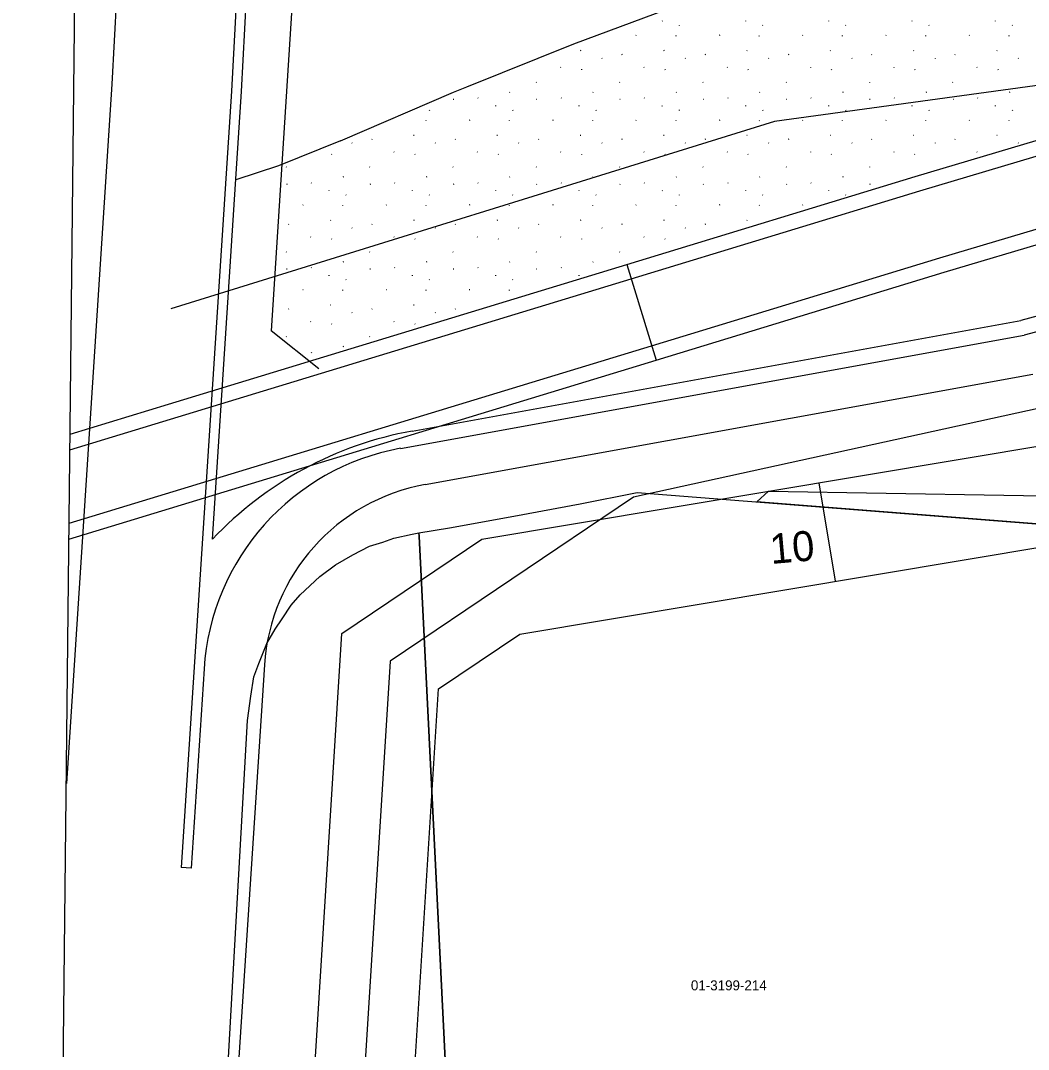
# Model space of a CAD drawing. Extents: x 419396 to 421519, y 4453567 to 4456767.
# Drawn here: x 420195.1 to 420295.9, y 4454723.5 to 4454826.5 of the extents above; entities that cross this region are included whole.
import ezdxf

# ---------------------------------------------------------------- set-up
doc = ezdxf.new("R2010")
doc.units = 0
for name, color, linetype in [('0_KADASTRO', 7, 'Continuous'), ('ADAKENARI1000', 7, 'Continuous'), ('ADAKENARI_ALT', 7, 'Continuous'), ('KALDIRIM', 7, 'Continuous'), ('KALDIRIM_ALT', 7, 'Continuous'), ('Level 20', 7, 'Continuous'), ('Level 29', 7, 'Continuous'), ('Level 41', 7, 'Continuous'), ('Level 9', 7, 'Continuous'), ('Y_Lejant', 7, 'Continuous')]:
    doc.layers.add(name, color=color, linetype=linetype)

msp = doc.modelspace()

# ---------------------------------------------------------------- linework, layer by layer
at = {"layer": '0_KADASTRO'}
for points in [[(420234.94, 4454775.21), (420237.99, 4454775.74), (420244.42, 4454776.89), (420251.07, 4454778.12), (420256.76, 4454779.25), (420319.17, 4454774.37), (420311.2, 4454734.75), (420308.37, 4454720.37), (420303.03, 4454697.63), (420301.63, 4454668.31), (420262.04, 4454668.65), (420253.02, 4454668.72), (420240.25, 4454669.24), (420238.25, 4454709.08), (420234.96, 4454774.88)], [(420268.76, 4454778.31), (420269.91, 4454779.39), (420317, 4454778.58), (420319.9, 4454775.53), (420318.59, 4454733.9), (420311.2, 4454734.75), (420319.17, 4454774.37)], [(420213.35, 4454677.72), (420217.79, 4454756.43), (420218.11, 4454758.88), (420218.44, 4454760.82), (420218.93, 4454762.13), (420219.72, 4454764.15), (420220.56, 4454765.58), (420221.26, 4454766.63), (420222.15, 4454767.98), (420223.07, 4454769.03), (420225.02, 4454770.85), (420226.61, 4454772.02), (420228.34, 4454773.02), (420229.99, 4454773.88), (420231.32, 4454774.3), (420232.44, 4454774.68), (420234.28, 4454775.09), (420234.94, 4454775.21), (420234.96, 4454774.88), (420238.25, 4454709.08), (420240.25, 4454669.24), (420233.01, 4454669.45), (420213.57, 4454670.16)]]:
    msp.add_lwpolyline(points, close=True, dxfattribs=at)
at = {"layer": 'ADAKENARI1000'}
for p, q in [((420217.2, 4454819.38), (420223.77, 4454944.07)), ((420225.07, 4454872.99), (420220.17, 4454795.43)), ((420250.45, 4454824.17), (420259.79, 4454827.64)), ((420239.73, 4454819.88), (420250.45, 4454824.17)), ((420238.4, 4454819.32), (420239.73, 4454819.88)), ((420214.29, 4454774.6), (420217.2, 4454819.38)), ((420227.09, 4454814.47), (420238.4, 4454819.32)), ((420284.6, 4454810.89), (420301.44, 4454815.91)), ((420227.09, 4454814.47), (420220.9, 4454811.95)), ((420220.9, 4454811.95), (420216.62, 4454810.55)), ((420255.74, 4454802.08), (420284.6, 4454810.89)), ((420287.49, 4454801.31), (420304.09, 4454806.26)), ((420255.74, 4454802.08), (420258.66, 4454792.52)), ((420258.66, 4454792.52), (420287.49, 4454801.31)), ((420312.54, 4454801.12), (420295.15, 4454796.47)), ((420234.26, 4454785.41), (420295.15, 4454796.47)), ((420224.94, 4454791.65), (420220.17, 4454795.43))]:
    msp.add_line(p, q, dxfattribs=at)
msp.add_arc((420240.79, 4454749.51), 36.49, 100.2941, 136.5562, dxfattribs=at)
at = {"layer": 'ADAKENARI_ALT'}
for p, q in [((420209.88, 4454788.09), (420255.74, 4454802.08)), ((420209.21, 4454777.43), (420258.66, 4454792.52)), ((420200.04, 4454785.09), (420209.88, 4454788.09)), ((420199.93, 4454774.6), (420209.21, 4454777.43))]:
    msp.add_line(p, q, dxfattribs=at)
at = {"layer": 'KALDIRIM'}
for p, q in [((420214.59, 4455016.89), (420204.22, 4454820.13)), ((420224.17, 4454970.66), (420216.2, 4454819.43)), ((420204.22, 4454820.13), (420199.67, 4454750.15)), ((420216.2, 4454819.43), (420211.15, 4454741.72)), ((420285.04, 4454809.45), (420301.84, 4454814.46)), ((420256.18, 4454800.65), (420285.04, 4454809.45)), ((420287.06, 4454802.75), (420303.69, 4454807.71)), ((420258.22, 4454793.95), (420287.06, 4454802.75)), ((420312.96, 4454799.67), (420295.48, 4454795.01)), ((420233.11, 4454783.68), (420295.48, 4454795.01)), ((420235.58, 4454780.06), (420296.35, 4454791.1)), ((420213.45, 4454761.61), (420212.15, 4454741.66)), ((420219.48, 4454762), (420213.98, 4454677.3)), ((420212.15, 4454741.66), (420211.15, 4454741.72))]:
    msp.add_line(p, q, dxfattribs=at)
for centre, radius in [((420237.4, 4454760.06), 24.01), ((420239.09, 4454760.73), 19.65)]:
    msp.add_arc(centre, radius, 100.2941, 176.2859, dxfattribs=at)
at = {"layer": 'KALDIRIM_ALT'}
for p, q in [((420200.03, 4454783.52), (420256.18, 4454800.65)), ((420199.95, 4454776.18), (420258.22, 4454793.95))]:
    msp.add_line(p, q, dxfattribs=at)
at = {"layer": 'Level 20'}
for p, q in [((420274.94, 4454780.23), (420276.59, 4454770.37)), ((420245.03, 4454765.08), (420309.65, 4454775.9)), ((420236.91, 4454759.61), (420245.03, 4454765.08)), ((420228.46, 4454624.35), (420236.91, 4454759.61))]:
    msp.add_line(p, q, dxfattribs=at)
at = {"layer": 'Level 29'}
for p, q in [((420241.24, 4454774.59), (420310.47, 4454786.18)), ((420227.24, 4454765.14), (420241.24, 4454774.59)), ((420218.24, 4454621.14), (420227.24, 4454765.14))]:
    msp.add_line(p, q, dxfattribs=at)
at = {"layer": 'Level 41'}
for p, q in [((420259.29, 4454826.42), (420259.3, 4454826.47)), ((420260.97, 4454826.04), (420260.99, 4454825.99)), ((420267.63, 4454826.42), (420267.63, 4454826.47)), ((420269.3, 4454826.04), (420269.33, 4454825.99)), ((420275.96, 4454826.42), (420275.96, 4454826.47)), ((420277.63, 4454826.04), (420277.66, 4454825.99)), ((420284.29, 4454826.42), (420284.3, 4454826.47)), ((420285.96, 4454826.04), (420285.99, 4454825.99)), ((420292.62, 4454826.42), (420292.63, 4454826.47)), ((420294.3, 4454826.04), (420294.32, 4454825.99)), ((420256.69, 4454825.02), (420256.65, 4454825)), ((420265.03, 4454825.02), (420264.98, 4454825)), ((420273.36, 4454825.02), (420273.31, 4454825)), ((420281.69, 4454825.02), (420281.64, 4454825)), ((420290.02, 4454825.02), (420289.98, 4454825)), ((420260.66, 4454824.95), (420260.67, 4454825)), ((420268.99, 4454824.95), (420269, 4454825)), ((420277.32, 4454824.95), (420277.33, 4454825)), ((420285.66, 4454824.95), (420285.66, 4454825)), ((420293.99, 4454824.95), (420294, 4454825)), ((420251.13, 4454823.49), (420251.08, 4454823.47)), ((420255.27, 4454823.09), (420255.22, 4454823.07)), ((420259.46, 4454823.49), (420259.41, 4454823.47)), ((420263.6, 4454823.09), (420263.55, 4454823.07)), ((420267.79, 4454823.49), (420267.74, 4454823.47)), ((420271.93, 4454823.09), (420271.88, 4454823.07)), ((420276.12, 4454823.49), (420276.08, 4454823.47)), ((420280.26, 4454823.09), (420280.22, 4454823.07)), ((420284.45, 4454823.49), (420284.41, 4454823.47)), ((420288.6, 4454823.09), (420288.55, 4454823.07)), ((420292.79, 4454823.49), (420292.74, 4454823.47)), ((420253.24, 4454822.74), (420253.27, 4454822.7)), ((420261.57, 4454822.74), (420261.6, 4454822.7)), ((420269.91, 4454822.74), (420269.93, 4454822.7)), ((420278.24, 4454822.74), (420278.27, 4454822.7)), ((420286.57, 4454822.74), (420286.6, 4454822.7)), ((420294.9, 4454822.74), (420294.93, 4454822.7)), ((420249.11, 4454821.84), (420249.13, 4454821.79)), ((420251.2, 4454821.62), (420251.22, 4454821.57)), ((420257.44, 4454821.84), (420257.47, 4454821.79)), ((420259.53, 4454821.62), (420259.56, 4454821.57)), ((420265.77, 4454821.84), (420265.8, 4454821.79)), ((420267.86, 4454821.62), (420267.89, 4454821.57)), ((420274.1, 4454821.84), (420274.13, 4454821.79)), ((420276.19, 4454821.62), (420276.22, 4454821.57)), ((420282.44, 4454821.84), (420282.46, 4454821.79)), ((420284.52, 4454821.62), (420284.55, 4454821.57)), ((420290.77, 4454821.84), (420290.8, 4454821.79)), ((420292.86, 4454821.62), (420292.89, 4454821.57)), ((420246.67, 4454820.34), (420246.7, 4454820.3)), ((420255, 4454820.34), (420255.03, 4454820.3)), ((420263.34, 4454820.34), (420263.36, 4454820.3)), ((420271.67, 4454820.34), (420271.7, 4454820.3)), ((420280, 4454820.34), (420280.03, 4454820.3)), ((420288.33, 4454820.34), (420288.36, 4454820.3)), ((420244.05, 4454819.33), (420244, 4454819.31)), ((420252.38, 4454819.33), (420252.34, 4454819.31)), ((420260.71, 4454819.33), (420260.67, 4454819.31)), ((420269.05, 4454819.33), (420269, 4454819.31)), ((420277.38, 4454819.33), (420277.33, 4454819.31)), ((420285.71, 4454819.33), (420285.66, 4454819.31)), ((420294.04, 4454819.33), (420294, 4454819.31)), ((420238.42, 4454818.6), (420238.37, 4454818.58)), ((420240.83, 4454818.76), (420240.86, 4454818.72)), ((420242.63, 4454817.93), (420242.64, 4454817.99)), ((420246.75, 4454818.6), (420246.71, 4454818.58)), ((420249.16, 4454818.76), (420249.19, 4454818.72)), ((420250.96, 4454817.93), (420250.97, 4454817.99)), ((420255.08, 4454818.6), (420255.04, 4454818.58)), ((420257.49, 4454818.76), (420257.52, 4454818.72)), ((420259.29, 4454817.93), (420259.3, 4454817.99)), ((420263.42, 4454818.6), (420263.37, 4454818.58)), ((420265.83, 4454818.76), (420265.85, 4454818.72)), ((420267.63, 4454817.93), (420267.63, 4454817.99)), ((420271.75, 4454818.6), (420271.7, 4454818.58)), ((420274.16, 4454818.76), (420274.19, 4454818.72)), ((420275.96, 4454817.93), (420275.96, 4454817.99)), ((420280.08, 4454818.6), (420280.03, 4454818.58)), ((420282.49, 4454818.76), (420282.52, 4454818.72)), ((420284.29, 4454817.93), (420284.3, 4454817.99)), ((420288.41, 4454818.6), (420288.37, 4454818.58)), ((420290.82, 4454818.76), (420290.85, 4454818.72)), ((420292.62, 4454817.93), (420292.63, 4454817.99)), ((420235.97, 4454817.55), (420236, 4454817.5)), ((420244.3, 4454817.55), (420244.33, 4454817.5)), ((420252.63, 4454817.55), (420252.66, 4454817.5)), ((420260.97, 4454817.55), (420260.99, 4454817.5)), ((420269.3, 4454817.55), (420269.33, 4454817.5)), ((420277.63, 4454817.55), (420277.66, 4454817.5)), ((420285.96, 4454817.55), (420285.99, 4454817.5)), ((420294.3, 4454817.55), (420294.32, 4454817.5)), ((420235.66, 4454816.46), (420235.67, 4454816.51)), ((420240.03, 4454816.53), (420239.98, 4454816.51)), ((420244, 4454816.46), (420244, 4454816.51)), ((420248.36, 4454816.53), (420248.32, 4454816.51)), ((420252.33, 4454816.46), (420252.34, 4454816.51)), ((420256.69, 4454816.53), (420256.65, 4454816.51)), ((420260.66, 4454816.46), (420260.67, 4454816.51)), ((420265.03, 4454816.53), (420264.98, 4454816.51)), ((420268.99, 4454816.46), (420269, 4454816.51)), ((420273.36, 4454816.53), (420273.31, 4454816.51)), ((420277.32, 4454816.46), (420277.33, 4454816.51)), ((420281.69, 4454816.53), (420281.64, 4454816.51)), ((420285.66, 4454816.46), (420285.66, 4454816.51)), ((420290.02, 4454816.53), (420289.98, 4454816.51)), ((420293.99, 4454816.46), (420294, 4454816.51)), ((420234.46, 4454815), (420234.41, 4454814.98)), ((420242.79, 4454815), (420242.75, 4454814.98)), ((420251.13, 4454815), (420251.08, 4454814.98)), ((420259.46, 4454815), (420259.41, 4454814.98)), ((420267.79, 4454815), (420267.74, 4454814.98)), ((420276.12, 4454815), (420276.08, 4454814.98)), ((420284.45, 4454815), (420284.41, 4454814.98)), ((420292.79, 4454815), (420292.74, 4454814.98)), ((420228.24, 4454814.25), (420228.27, 4454814.21)), ((420230.27, 4454814.61), (420230.22, 4454814.58)), ((420236.58, 4454814.25), (420236.61, 4454814.21)), ((420238.6, 4454814.61), (420238.56, 4454814.58)), ((420244.91, 4454814.25), (420244.94, 4454814.21)), ((420246.93, 4454814.61), (420246.89, 4454814.58)), ((420253.24, 4454814.25), (420253.27, 4454814.21)), ((420255.27, 4454814.61), (420255.22, 4454814.58)), ((420261.57, 4454814.25), (420261.6, 4454814.21)), ((420263.6, 4454814.61), (420263.55, 4454814.58)), ((420269.91, 4454814.25), (420269.93, 4454814.21)), ((420271.93, 4454814.61), (420271.88, 4454814.58)), ((420278.24, 4454814.25), (420278.27, 4454814.21)), ((420280.26, 4454814.61), (420280.22, 4454814.58)), ((420286.57, 4454814.25), (420286.6, 4454814.21)), ((420288.6, 4454814.61), (420288.55, 4454814.58)), ((420294.9, 4454814.25), (420294.93, 4454814.21)), ((420226.2, 4454813.13), (420226.23, 4454813.09)), ((420232.44, 4454813.35), (420232.47, 4454813.31)), ((420234.53, 4454813.13), (420234.56, 4454813.09)), ((420240.77, 4454813.35), (420240.8, 4454813.31)), ((420242.86, 4454813.13), (420242.89, 4454813.09)), ((420249.11, 4454813.35), (420249.13, 4454813.31)), ((420251.2, 4454813.13), (420251.22, 4454813.09)), ((420257.44, 4454813.35), (420257.47, 4454813.31)), ((420259.53, 4454813.13), (420259.56, 4454813.09)), ((420265.77, 4454813.35), (420265.8, 4454813.31)), ((420267.86, 4454813.13), (420267.89, 4454813.09)), ((420274.1, 4454813.35), (420274.13, 4454813.31)), ((420276.19, 4454813.13), (420276.22, 4454813.09)), ((420282.44, 4454813.35), (420282.46, 4454813.31)), ((420284.52, 4454813.13), (420284.55, 4454813.09)), ((420290.77, 4454813.35), (420290.8, 4454813.31)), ((420221.67, 4454811.85), (420221.7, 4454811.81)), ((420230.01, 4454811.85), (420230.03, 4454811.81)), ((420238.34, 4454811.85), (420238.37, 4454811.81)), ((420246.67, 4454811.85), (420246.7, 4454811.81)), ((420255, 4454811.85), (420255.03, 4454811.81)), ((420263.34, 4454811.85), (420263.36, 4454811.81)), ((420271.67, 4454811.85), (420271.7, 4454811.81)), ((420280, 4454811.85), (420280.03, 4454811.81)), ((420227.39, 4454810.84), (420227.34, 4454810.82)), ((420235.72, 4454810.84), (420235.67, 4454810.82)), ((420244.05, 4454810.84), (420244, 4454810.82)), ((420252.38, 4454810.84), (420252.34, 4454810.82)), ((420260.71, 4454810.84), (420260.67, 4454810.82)), ((420269.05, 4454810.84), (420269, 4454810.82)), ((420277.38, 4454810.84), (420277.33, 4454810.82)), ((420221.76, 4454810.11), (420221.71, 4454810.09)), ((420224.16, 4454810.27), (420224.19, 4454810.23)), ((420230.09, 4454810.11), (420230.04, 4454810.09)), ((420232.5, 4454810.27), (420232.52, 4454810.23)), ((420238.42, 4454810.11), (420238.37, 4454810.09)), ((420240.83, 4454810.27), (420240.86, 4454810.23)), ((420246.75, 4454810.11), (420246.71, 4454810.09)), ((420249.16, 4454810.27), (420249.19, 4454810.23)), ((420255.08, 4454810.11), (420255.04, 4454810.09)), ((420257.49, 4454810.27), (420257.52, 4454810.23)), ((420263.42, 4454810.11), (420263.37, 4454810.09)), ((420265.83, 4454810.27), (420265.85, 4454810.23)), ((420271.75, 4454810.11), (420271.7, 4454810.09)), ((420274.16, 4454810.27), (420274.19, 4454810.23)), ((420280.08, 4454810.11), (420280.03, 4454810.09)), ((420282.49, 4454810.27), (420282.51, 4454810.25)), ((420225.96, 4454809.45), (420225.97, 4454809.5)), ((420227.64, 4454809.06), (420227.67, 4454809.02)), ((420234.3, 4454809.45), (420234.3, 4454809.5)), ((420235.97, 4454809.06), (420236, 4454809.02)), ((420242.63, 4454809.45), (420242.64, 4454809.5)), ((420244.3, 4454809.06), (420244.33, 4454809.02)), ((420250.96, 4454809.45), (420250.97, 4454809.5)), ((420252.63, 4454809.06), (420252.66, 4454809.02)), ((420259.29, 4454809.45), (420259.3, 4454809.5)), ((420260.97, 4454809.06), (420260.99, 4454809.02)), ((420267.63, 4454809.45), (420267.63, 4454809.5)), ((420269.3, 4454809.06), (420269.33, 4454809.02)), ((420275.96, 4454809.45), (420275.96, 4454809.5)), ((420277.63, 4454809.06), (420277.66, 4454809.02)), ((420223.37, 4454808.05), (420223.32, 4454808.02)), ((420227.33, 4454807.97), (420227.34, 4454808.02)), ((420231.7, 4454808.05), (420231.65, 4454808.02)), ((420235.66, 4454807.97), (420235.67, 4454808.02)), ((420240.03, 4454808.05), (420239.98, 4454808.02)), ((420244, 4454807.97), (420244, 4454808.02)), ((420248.36, 4454808.05), (420248.32, 4454808.02)), ((420252.33, 4454807.97), (420252.34, 4454808.02)), ((420256.69, 4454808.05), (420256.65, 4454808.02)), ((420260.66, 4454807.97), (420260.67, 4454808.02)), ((420265.03, 4454808.05), (420264.98, 4454808.02)), ((420268.99, 4454807.97), (420269, 4454808.02)), ((420273.36, 4454808.05), (420273.31, 4454808.02)), ((420226.13, 4454806.51), (420226.08, 4454806.49)), ((420234.46, 4454806.51), (420234.41, 4454806.49)), ((420242.79, 4454806.51), (420242.75, 4454806.49)), ((420251.13, 4454806.51), (420251.08, 4454806.49)), ((420259.46, 4454806.51), (420259.41, 4454806.49)), ((420267.79, 4454806.51), (420267.74, 4454806.49)), ((420221.94, 4454806.12), (420221.89, 4454806.09)), ((420228.24, 4454805.76), (420228.27, 4454805.72)), ((420230.27, 4454806.12), (420230.22, 4454806.09)), ((420236.58, 4454805.76), (420236.61, 4454805.72)), ((420238.6, 4454806.12), (420238.56, 4454806.09)), ((420244.91, 4454805.76), (420244.94, 4454805.72)), ((420246.93, 4454806.12), (420246.89, 4454806.09)), ((420253.24, 4454805.76), (420253.27, 4454805.72)), ((420255.27, 4454806.12), (420255.22, 4454806.09)), ((420261.57, 4454805.76), (420261.6, 4454805.72)), ((420263.6, 4454806.12), (420263.55, 4454806.09)), ((420224.11, 4454804.86), (420224.14, 4454804.82)), ((420226.2, 4454804.64), (420226.23, 4454804.6)), ((420232.44, 4454804.86), (420232.47, 4454804.82)), ((420234.53, 4454804.64), (420234.56, 4454804.6)), ((420240.77, 4454804.86), (420240.8, 4454804.82)), ((420242.86, 4454804.64), (420242.89, 4454804.6)), ((420249.11, 4454804.86), (420249.13, 4454804.82)), ((420251.2, 4454804.64), (420251.22, 4454804.6)), ((420257.44, 4454804.86), (420257.47, 4454804.82)), ((420259.53, 4454804.64), (420259.56, 4454804.6)), ((420221.67, 4454803.36), (420221.7, 4454803.32)), ((420227.39, 4454802.35), (420227.34, 4454802.33)), ((420230.01, 4454803.36), (420230.03, 4454803.32)), ((420235.72, 4454802.35), (420235.67, 4454802.33)), ((420238.34, 4454803.36), (420238.37, 4454803.32)), ((420244.05, 4454802.35), (420244, 4454802.33)), ((420246.67, 4454803.36), (420246.7, 4454803.32)), ((420252.38, 4454802.35), (420252.34, 4454802.33)), ((420255, 4454803.36), (420255.03, 4454803.32)), ((420221.76, 4454801.62), (420221.71, 4454801.6)), ((420224.16, 4454801.79), (420224.19, 4454801.74)), ((420230.09, 4454801.62), (420230.04, 4454801.6)), ((420232.5, 4454801.79), (420232.52, 4454801.74)), ((420238.42, 4454801.62), (420238.37, 4454801.6)), ((420240.83, 4454801.79), (420240.86, 4454801.74)), ((420246.75, 4454801.62), (420246.71, 4454801.6)), ((420249.16, 4454801.79), (420249.19, 4454801.74)), ((420225.96, 4454800.96), (420225.97, 4454801.01)), ((420227.64, 4454800.57), (420227.67, 4454800.53)), ((420234.3, 4454800.96), (420234.3, 4454801.01)), ((420235.97, 4454800.57), (420236, 4454800.53)), ((420242.63, 4454800.96), (420242.64, 4454801.01)), ((420244.3, 4454800.57), (420244.33, 4454800.53)), ((420250.96, 4454800.96), (420250.97, 4454801.01)), ((420223.37, 4454799.56), (420223.32, 4454799.53)), ((420227.33, 4454799.48), (420227.34, 4454799.53)), ((420231.7, 4454799.56), (420231.65, 4454799.53)), ((420235.66, 4454799.48), (420235.67, 4454799.53)), ((420240.03, 4454799.56), (420239.98, 4454799.53)), ((420244, 4454799.48), (420244, 4454799.53)), ((420221.94, 4454797.63), (420221.89, 4454797.61)), ((420226.13, 4454798.02), (420226.08, 4454798)), ((420228.24, 4454797.28), (420228.27, 4454797.23)), ((420230.27, 4454797.63), (420230.22, 4454797.61)), ((420234.46, 4454798.02), (420234.41, 4454798)), ((420236.58, 4454797.28), (420236.61, 4454797.23)), ((420238.6, 4454797.63), (420238.56, 4454797.61)), ((420224.11, 4454796.37), (420224.14, 4454796.33)), ((420232.44, 4454796.37), (420232.47, 4454796.33)), ((420226.2, 4454796.15), (420226.23, 4454796.11)), ((420234.53, 4454796.15), (420234.56, 4454796.11)), ((420221.67, 4454794.88), (420221.7, 4454794.83)), ((420230.01, 4454794.88), (420230.03, 4454794.83)), ((420224.16, 4454793.3), (420224.19, 4454793.25)), ((420227.39, 4454793.86), (420227.34, 4454793.84))]:
    msp.add_line(p, q, dxfattribs=at)
at = {"layer": 'Level 9'}
for p, q in [((420335.35, 4454825.3), (420270.51, 4454816.4)), ((420270.51, 4454816.4), (420210.11, 4454797.65))]:
    msp.add_line(p, q, dxfattribs=at)
msp.add_lwpolyline([(420624.43, 4454853.53), (420524.26, 4454837.53), (420256.41, 4454778.79), (420232.07, 4454762.38), (420226.4, 4454671.58), (420198.86, 4454673.3)], dxfattribs=at)
at = {"layer": 'Y_Lejant'}
msp.add_lwpolyline([(420209.76, 4455704.6), (421518.56, 4455690.86), (421518.56, 4454302.65), (420195.09, 4454316.54)], close=True, dxfattribs=at)

# ---------------------------------------------------------------- texts
at = {"layer": '0_KADASTRO'}
msp.add_text('01-3199-214', height=1, dxfattribs=at).set_placement((420262.15, 4454729.43))
at = {"layer": 'Level 20'}
msp.add_text('10', height=3, rotation=5.0366, dxfattribs=at).set_placement((420270.18, 4454772.1))

doc.saveas('drawing.dxf')
